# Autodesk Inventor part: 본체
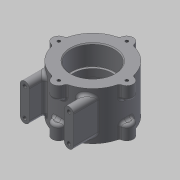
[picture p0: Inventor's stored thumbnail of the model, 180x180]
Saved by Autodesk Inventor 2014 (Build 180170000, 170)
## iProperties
Created: 2015-03
Part Number: 본체
Material: Generic
Document SubType Name: Modeling
Designer: Administrator
Density: 1 g/cm^3
Appearance: Default
Author: Administrator
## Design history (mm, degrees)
sketch "스케치1"
  geometry: C1 r 37 at (0, 0); 1 further point
  constraints: 1 centre point, 1 coincident
  dimensions: "d0" = 74 diameter of C1
extrude "돌출1" new body sketch "스케치1" stored distance "d1" = 52; taper "d2" = 0 deg
sketch "스케치2"
  geometry: C1 r 37 at (0, 0) reference; C2 r 23.5 at (0, 0)
  constraints: 1 centre point, 1 coincident
  dimensions: "d5" = 47 diameter of C2
extrude "돌출2" cut sketch "스케치2" distance "d6" = 22; taper "d7" = 0 deg
sketch "스케치3"
  geometry: C1 r 23.5 at (0, 0) reference; C2 r 21 at (0, 0)
  constraints: 1 centre point, 1 coincident
  dimensions: "d8" = 42 diameter of C2
extrude "돌출3" cut sketch "스케치3" distance "d9" = 8; taper "d10" = 0 deg
sketch "스케치4"
  geometry: C1 r 37 at (0, 0) reference; C2 r 23.5 at (0, 0)
  constraints: 1 centre point, 1 coincident
  dimensions: "d11" = 47 diameter of C2
extrude "돌출4" cut sketch "스케치4" distance "d12" = 22; taper "d13" = 0 deg
sketch "스케치5"
  geometry: C1 r 23.5 at (0, 0) reference; C2 r 7 at (0, 37); C3 r 7 at (-37, 0); C4 r 7 at (0, -37); C5 r 7 at (37, 0); A1 r 37 centre (0, 0) between (0, 37) and (-37, 0) reference
  constraints: 4 centre point, 4 point on circle, 2 horizontal alignment, 2 vertical alignment
  dimensions: "d15" = 7 radius of C2; "d16" = 7 radius of C3; "d17" = 7 radius of C4; "d18" = 7 radius of C5
extrude "돌출5" join sketch "스케치5" distance "d19" = 15; taper "d20" = 0 deg
sketch "스케치6"
  geometry: A1 r 7 centre (0, 37) between (6.969, 36.338) and (-6.969, 36.338) reference; A2 r 7 centre (-37, 0) between (-36.338, 6.969) and (-36.338, -6.969) reference; A3 r 7 centre (0, -37) between (-6.969, -36.338) and (6.969, -36.338) reference; A4 r 7 centre (37, 0) between (36.338, -6.969) and (36.338, 6.969) reference; 4 further points
  constraints: 4 coincident
hole "구멍1" sketch "스케치6" at (0, 37), (-37, 0), (0, -37), (37, 0) diameter "d21" = 3.242; stored, may be unused: countersink angle "d25" = 90 deg, drill point angle "d27" = 118 deg; dims "d22" = 8, "d23" = 4, "d24" = 2, "d26" = 11
sketch "스케치7"
  geometry: L1 (-29, -22.978)-(-29, -50); L2 (-29, -50)-(-19, -50); L3 (-19, -50)-(-19, -31.749); L4 (19, -31.749)-(19, -50); L5 (19, -50)-(29, -50); L6 (29, -50)-(29, -22.978); A1 r 37 centre (0, 0) between (-36.338, -6.969) and (-6.969, -36.338) reference; A2 r 37 centre (0, 0) between (6.969, -36.338) and (36.338, -6.969) reference; 1 further point
  constraints: 12 end point, 4 point on circle, 3 parallel, 2 perpendicular, 1 collinear, 1 vertical
  dimensions: "d28" = 58 distance between parallel lines of L6 L1; "d29" = 50 distance from line of L5 point (0, 0); "d30" = 29 distance from line of point (0, 0) L1; "d31" = 10 distance between parallel lines of L3 L1; "d32" = 10 distance between parallel lines of L6 L4
extrude "돌출6" join sketch "스케치7" stored distance "d33" = 40; taper "d34" = 0 deg
fillet "모깎기1" dims "d35" = 5
sketch "스케치9"
  geometry: A1 r 5 centre (0, 0) between (-5, 0) and (5, 0) reference; A2 r 5 centre (0, 30) between (5, 30) and (-5, 30) reference; 3 further points
  constraints: 2 coincident
hole "구멍2" sketch "스케치9" at (0, 30), (0, 0) diameter "d36" = 4.134; stored, may be unused: countersink angle "d40" = 90 deg, drill point angle "d42" = 118 deg; dims "d37" = 6, "d38" = 4, "d39" = 2, "d41" = 8
sketch "스케치10"
  geometry: L1 (0, 0)-(-37, 0); L2 (0, 0)-(0, 37); L3 (0, 0)-(-26.163, 26.163); A1 r 37 centre (0, 0) between (-6.969, 36.338) and (-36.338, 6.969) reference; A2 r 37 centre (0, 0) between (-36.338, 6.969) and (-36.338, -6.969) reference; A3 r 37 centre (0, 0) between (6.969, 36.338) and (-6.969, 36.338) reference; 2 further points
  constraints: 6 end point, 3 point on circle, 1 coincident
  dimensions: "d44" = 45 deg angle of L1 L3
node "작업 평면1"
sketch "스케치11"
  geometry: L1 (-20.767, -26)-(20.767, -26) reference; 2 further points
  constraints: 1 coincident, 1 other
  dimensions: "d45" = 26 distance from line of point (0, 0) L1
feature "엠보싱1" sketch "스케치11" dims "d46" = 0.5, "d47" = 0
chamfer "모따기1" distance "d48" = 1; stored, may be unused: second distance "d49" = 2, angle "d50" = 45 deg
fillet "모깎기2" dims "d51" = 0.3
fillet "모깎기3" dims "d52" = 3
fillet "모깎기6" dims "d55" = 3
fillet "모깎기7" dims "d56" = 3
node "솔리드1"
mirror "대칭1"
mirror "대칭2"
